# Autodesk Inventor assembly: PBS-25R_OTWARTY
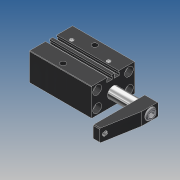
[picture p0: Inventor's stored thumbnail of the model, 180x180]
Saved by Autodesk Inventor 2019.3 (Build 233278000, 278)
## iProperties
Created: 2010-02
Part Number: PBS-25R_OTWARTY
Material: Ogólny
Document SubType Name: Assembly
Designer: CADENGINEERING4
Sending System: PRO/ENGINEER BY PARAMETRIC TECHNOLOGY CORPORATION, 2007170
Preprocessor: PRO/ENGINEER BY PARAMETRIC TECHNOLOGY CORPORATION, 2007170
Title: PSB-25_ASM
Author: Administrator
Revision Number: 1LAST_VERSION
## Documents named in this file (6)
- E:\SERWER_ZAPAS\Pneumatic\PSB PNEUMATIC SWING\PSB-25\PBS-25R_OTWARTY.iam
- E:\SERWER_ZAPAS\Pneumatic\PSB PNEUMATIC SWING\PSB-25\PSB-25BT.ipt
- E:\SERWER_ZAPAS\Pneumatic\PSB PNEUMATIC SWING\PSB-25\PSB-25HSG.ipt
- E:\SERWER_ZAPAS\Pneumatic\PSB PNEUMATIC SWING\PSB-25\PSB-25HG.ipt
- E:\SERWER_ZAPAS\Pneumatic\PSB PNEUMATIC SWING\PSB-25\PSB-25YB.ipt
- E:\SERWER_ZAPAS\Pneumatic\PSB PNEUMATIC SWING\PSB-25\M8X20.ipt
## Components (5 placed, 5 different names)
1. PSB-25BT_0 — Równoległe:1, Zestawiające:1, Zestawiające:2, Zestawiające:3, Kątowe:1
2. PSB-25HSG_1 — Zestawiające:2, Zestawiające:3, Zestawiające:4, Zestawiające:5
3. PSB-25HG_2 — Równoległe:1, Zestawiające:1
4. PSB-25YB_3 — Zestawiające:4, Zestawiające:5, Zestawiające:6, Zestawiające:7, Kątowe:1
5. M8X20_4 — Zestawiające:6, Zestawiające:7
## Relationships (9: Mate 7, Flush 1, Angle 1)
- Równoległe:1 [Flush]: PSB-25BT_0 ↔ PSB-25HG_2
- Zestawiające:1 [Mate]: PSB-25BT_0 ↔ PSB-25HG_2
- Zestawiające:2 [Mate]: PSB-25BT_0 ↔ PSB-25HSG_1
- Zestawiające:3 [Mate]: PSB-25BT_0 ↔ PSB-25HSG_1
- Zestawiające:4 [Mate]: PSB-25HSG_1 ↔ PSB-25YB_3
- Zestawiające:5 [Mate]: PSB-25HSG_1 ↔ PSB-25YB_3
- Zestawiające:6 [Mate]: PSB-25YB_3 ↔ M8X20_4
- Zestawiające:7 [Mate]: PSB-25YB_3 ↔ M8X20_4
- Kątowe:1 [Angle]: PSB-25BT_0 ↔ PSB-25YB_3
